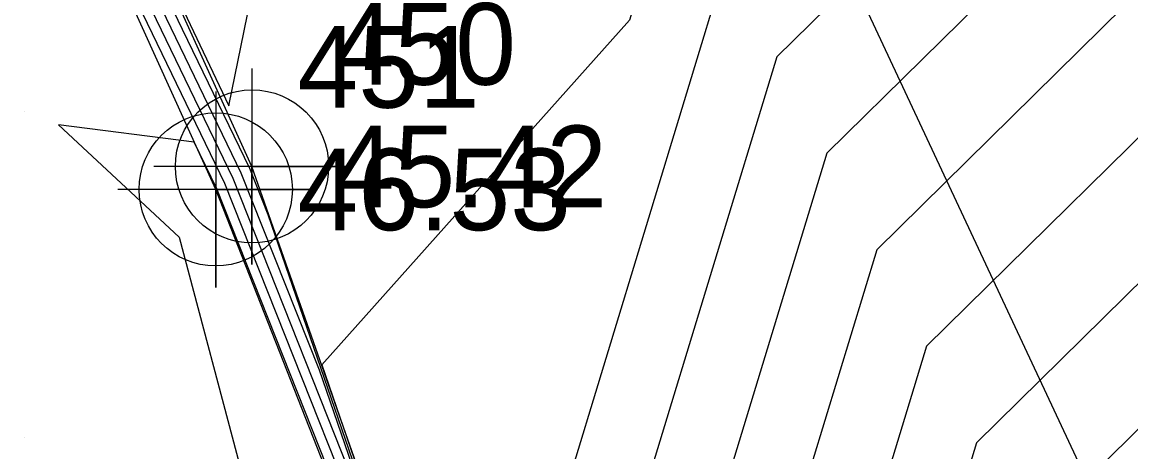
# Model space of a CAD drawing. Extents: x 2090860 to 2091277, y 159470 to 160080.
# Drawn here: x 2091009.91 to 2091043.83, y 159779.57 to 159792.72 of the extents above; entities that cross this region are included whole.
import ezdxf

# ---------------------------------------------------------------- set-up
doc = ezdxf.new("R2010")
doc.units = 0
for name, color, linetype in [('DTM Contours Major', 7, 'Continuous'), ('DTM Contours Minor', 7, 'Continuous'), ('Exist DTM Breakline', 7, 'Continuous'), ('Exist DTM Breakline Cogo Elevation', 7, 'Continuous'), ('Exist DTM Breakline Cogo Number', 7, 'Continuous'), ('Exist DTM Breakline Cogo Point CELL', 7, 'Continuous'), ('Exist DTM QL2 LIDAR Elevation Point', 7, 'Continuous'), ('Exist Structure Major Deck Tunnel Box Culvert', 7, 'Continuous')]:
    doc.layers.add(name, color=color, linetype=linetype)

msp = doc.modelspace()

# ---------------------------------------------------------------- linework, layer by layer
at = {"layer": 'DTM Contours Major'}
for points in [[(2091039.965, 159928.181), (2091029.722, 159901.932), (2091029.836, 159894.927), (2091030.644, 159893.334), (2091041.091, 159874.328), (2091046.743, 159874.324), (2091051.278, 159874.322), (2091048.513, 159861.61), (2091048.021, 159860.923), (2091052.613, 159846.512), (2091052.563, 159846.236), (2091064.701, 159822.801), (2091063.816, 159819.49), (2091056.743, 159812.832), (2091055.874, 159811.447), (2091055.801, 159811.406), (2091054.881, 159810.97), (2091050.569, 159808.882), (2091033.907, 159797.012), (2091031.476, 159794.619), (2091026.533, 159778.36)], [(2091091.582, 159898.637), (2091075.464, 159895.754), (2091071.361, 159891.649), (2091065.515, 159864.769), (2091059.162, 159855.905), (2091062.527, 159845.344), (2091062.382, 159844.528), (2091071.24, 159827.424), (2091068.468, 159817.052), (2091062.553, 159811.484), (2091060.259, 159801.479), (2091046.876, 159791.945), (2091037.586, 159782.801), (2091031.987, 159764.384), (2091026.688, 159760.214), (2091021.294, 159752.688), (2091014.874, 159747.469), (2091001.671, 159730.125), (2090998.416, 159727.263), (2090990.823, 159719.668), (2090976.25, 159706.989)], [(2091020.583, 159777.303), (2091016.37, 159787.941), (2091005.234, 159810.993), (2091004.46, 159811.092), (2091002.403, 159797.597), (2091000.773, 159790), (2091001.026, 159788.974), (2091000, 159789.35), (2090993.373, 159786.627), (2090993.61, 159780), (2090991.192, 159778.808)]]:
    msp.add_lwpolyline(points, dxfattribs=at)
at = {"layer": 'DTM Contours Minor'}
for points in [[(2090953.056, 159921.956), (2090965.045, 159895.337), (2090965.357, 159894.662), (2090965.917, 159893.402), (2090966.117, 159891.569), (2090966.399, 159891.209), (2090966.744, 159891.353), (2090970.598, 159883.648), (2090979.253, 159865.886), (2090979.998, 159864.343), (2090992.069, 159839.553), (2090993.271, 159837.069), (2090997.157, 159829.086), (2091001.847, 159819.434), (2091003.887, 159815.198), (2091014.815, 159792.51), (2091016.869, 159788.257), (2091017.431, 159786.838), (2091024.63, 159765.903)], [(2091026.968, 159913.295), (2091027.29, 159893.598), (2091029.561, 159889.119), (2091036.393, 159876.69), (2091042.848, 159864.079), (2091045.034, 159860.22), (2091047.258, 159855.832), (2091050.134, 159846.804), (2091050.109, 159846.662), (2091063.066, 159821.645), (2091062.653, 159820.099), (2091059.35, 159816.99), (2091056.004, 159811.656), (2091055.725, 159811.498), (2091052.183, 159809.82), (2091035.577, 159801.778), (2091030.665, 159798.279), (2091029.949, 159797.574), (2091028.492, 159792.781), (2091019.078, 159782.234), (2091024.701, 159765.882)], [(2090957.425, 159912.812), (2090965.766, 159894.719), (2090966.215, 159893.707), (2090967.091, 159891.809), (2090969.426, 159886.946), (2090975.022, 159875.464), (2090981.876, 159861.269), (2090989.438, 159845.741), (2090994.696, 159834.875), (2090997.493, 159829.13), (2091000.868, 159822.182), (2091004.151, 159815.366), (2091012.999, 159796.996), (2091016.233, 159790.161), (2091018.49, 159801.202)], [(2091085.63, 159904.476), (2091061.277, 159900.12), (2091060.882, 159899.725), (2091052.763, 159862.4), (2091050.806, 159859.669), (2091055.091, 159846.22), (2091055.018, 159845.809), (2091066.336, 159823.957), (2091064.979, 159818.88), (2091057.025, 159811.393), (2091056.616, 159809.613), (2091037.15, 159795.745), (2091033.004, 159791.665), (2091025.134, 159765.782), (2091024.911, 159765.606), (2091017.656, 159755.482), (2091016.238, 159754.329), (2090999.201, 159731.949), (2090995.001, 159728.257), (2090991.695, 159724.95), (2090972.197, 159707.986)], [(2091087.614, 159902.53), (2091066.006, 159898.665), (2091064.375, 159897.033), (2091057.014, 159863.189), (2091053.591, 159858.414), (2091057.57, 159845.928), (2091057.473, 159845.382), (2091067.971, 159825.113), (2091066.142, 159818.271), (2091058.867, 159811.424), (2091057.831, 159806.902), (2091040.392, 159794.478), (2091034.531, 159788.71), (2091027.419, 159765.316), (2091025.503, 159763.809), (2091018.868, 159754.551), (2091015.783, 159752.042), (2091000.024, 159731.341), (2090996.139, 159727.925), (2090991.404, 159723.189), (2090973.548, 159707.654)], [(2091089.598, 159900.583), (2091070.735, 159897.209), (2091067.868, 159894.341), (2091061.264, 159863.979), (2091056.377, 159857.16), (2091060.048, 159845.636), (2091059.927, 159844.955), (2091069.606, 159826.269), (2091067.305, 159817.661), (2091060.71, 159811.454), (2091059.045, 159804.19), (2091043.634, 159793.212), (2091036.059, 159785.755), (2091029.703, 159764.85), (2091026.095, 159762.012), (2091020.081, 159753.62), (2091015.328, 159749.755), (2091000.847, 159730.733), (2090997.277, 159727.594), (2090991.114, 159721.429), (2090974.899, 159707.322)], [(2091093.566, 159896.69), (2091080.192, 159894.298), (2091074.854, 159888.957), (2091069.765, 159865.558), (2091061.947, 159854.65), (2091065.005, 159845.052), (2091064.837, 159844.101), (2091072.875, 159828.58), (2091069.631, 159816.443), (2091064.396, 159811.515), (2091061.473, 159798.767), (2091050.118, 159790.678), (2091039.113, 159779.846), (2091034.271, 159763.918), (2091027.28, 159758.417), (2091022.507, 159751.757), (2091014.419, 159745.182), (2091002.494, 159729.516), (2090999.554, 159726.932), (2090990.532, 159717.907), (2090977.601, 159706.657)], [(2091095.549, 159894.744), (2091084.921, 159892.843), (2091078.348, 159886.266), (2091074.015, 159866.348), (2091064.733, 159853.396), (2091067.484, 159844.76), (2091067.291, 159843.674), (2091074.51, 159829.736), (2091070.794, 159815.833), (2091066.238, 159811.545), (2091062.688, 159796.056), (2091053.36, 159789.411), (2091040.641, 159776.892), (2091036.555, 159763.452), (2091027.872, 159756.62), (2091023.719, 159750.826), (2091013.964, 159742.895), (2091003.317, 159728.908), (2091000.692, 159726.601), (2090990.241, 159716.147), (2090978.952, 159706.325)], [(2091024.559, 159765.924), (2091019.007, 159782.07), (2091016.62, 159788.099), (2091007.896, 159806.158), (2091003.623, 159815.029), (2091002.826, 159816.685), (2091000.261, 159821.963), (2090995.168, 159818.049), (2090991.625, 159818.375), (2090991.782, 159810), (2090995.432, 159804.568), (2090990, 159801.203), (2090989.571, 159800.429), (2090989.322, 159800), (2090990, 159797.747), (2090992.013, 159790), (2090990.586, 159789.414), (2090990.922, 159780), (2090990.305, 159779.695), (2090990, 159779.105)], [(2091022.158, 159772.536), (2091016.12, 159787.782), (2091010.208, 159800.022), (2091007.269, 159800.396), (2091006.255, 159793.745), (2091005.452, 159790), (2091007.239, 159782.761), (2091000, 159785.418), (2090996.161, 159783.839), (2090996.298, 159780), (2090992.08, 159777.92)], [(2091023.734, 159767.768), (2091015.871, 159787.624), (2091015.181, 159789.051), (2091011.022, 159789.581), (2091014.717, 159786.143), (2091018.577, 159771.611)]]:
    msp.add_lwpolyline(points, dxfattribs=at)
at = {"layer": 'Exist DTM Breakline'}
for points in [[(2090970.603, 159708.378), (2090997.094, 159733.506), (2091024.833, 159765.843), (2091016.946, 159788.306), (2090998.355, 159829.241)], [(2090970.238, 159708.524), (2090995.777, 159734.72), (2091024.32, 159765.995), (2091015.838, 159787.603), (2090997.039, 159829.071)]]:
    msp.add_lwpolyline(points, dxfattribs=at)
at = {"layer": 'Exist DTM Breakline Cogo Point CELL'}
for points in [[(2091016.946, 159791.306), (2091016.946, 159785.306), (2091016.946, 159788.306), (2091019.946, 159788.306), (2091013.946, 159788.306)], [(2091015.838, 159790.603), (2091015.838, 159784.603), (2091015.838, 159787.603), (2091018.838, 159787.603), (2091012.838, 159787.603)]]:
    msp.add_lwpolyline(points, dxfattribs=at)
for centre in [(2091016.946, 159788.306), (2091015.838, 159787.603)]:
    msp.add_circle(centre, 2.344, dxfattribs=at)
at = {"layer": 'Exist DTM QL2 LIDAR Elevation Point'}
for p, q in [((2091010, 159790), (2091010, 159790)), ((2091010, 159780), (2091010, 159780))]:
    msp.add_line(p, q, dxfattribs=at)
at = {"layer": 'Exist Structure Major Deck Tunnel Box Culvert'}
msp.add_lwpolyline([(2091083.939, 159746.358), (2091062.342, 159736.259), (2091031.248, 159802.748), (2091052.743, 159813.103)], close=True, dxfattribs=at)

# ---------------------------------------------------------------- texts
at = {"layer": 'Exist DTM Breakline Cogo Elevation'}
for s, p in [('45.42', (2091019.446, 159787.056)), ('46.53', (2091018.338, 159786.353))]:
    msp.add_text(s, height=2.5, dxfattribs=at).set_placement(p)
at = {"layer": 'Exist DTM Breakline Cogo Number'}
for s, p in [('450', (2091019.446, 159790.806)), ('451', (2091018.338, 159790.103))]:
    msp.add_text(s, height=2.5, dxfattribs=at).set_placement(p)

doc.saveas('drawing.dxf')
